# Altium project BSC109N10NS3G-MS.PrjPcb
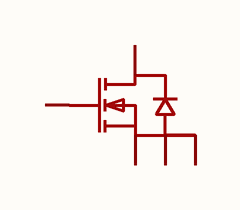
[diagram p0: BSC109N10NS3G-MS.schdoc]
1 sheet, 1 parts. Net scope: global (net labels, ports and power ports of the same name join across sheets).

## Sheet BSC109N10NS3G-MS.schdoc
size 127 x 101 mm

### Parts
Q?  bsc109n10ns3g-ms  [TDSON-8_L5.9-W5.2-P1.27-BL-1]  (value not drawn)

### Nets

Not connected (* = marked no-connect by the designer): Q? 1(S) 2(S) 3(S) 4(G) 5(D)

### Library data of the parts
Q? = bsc109n10ns3g-ms: 数量:1个N沟道;漏源电压(Vdss):100V;连续漏极电流(Id):75A;导通电阻(RDS(on)):7.3mΩ@10V;耗散功率(Pd):97W;阈值电压(Vgs(th)):1.6V;; Manufacturer: MSKSEMI(美森科); AddInBom: yes; ModelId: 6d3ef2b64d5a4f2dbd2ee02e0c7053d2; ModelTransform: 205.511,242.1255,0,0,0,0,0,42.913,0; Number: 1个N沟道; Drain to Source Voltage: 100V; Current - Continuous Drain(Id): 75A; Pd - Power Dissipation: 97W; Gate Threshold Voltage (Vgs(th)): 1.6V; Gate Charge(Qg): 39.4nC; Input Capacitance(Ciss): 2.046nF; Reverse Transfer Capacitance (Crss@Vds): 25pF; Type: N沟道; Output Capacitance(Coss): 865pF; Vgs: ±20V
